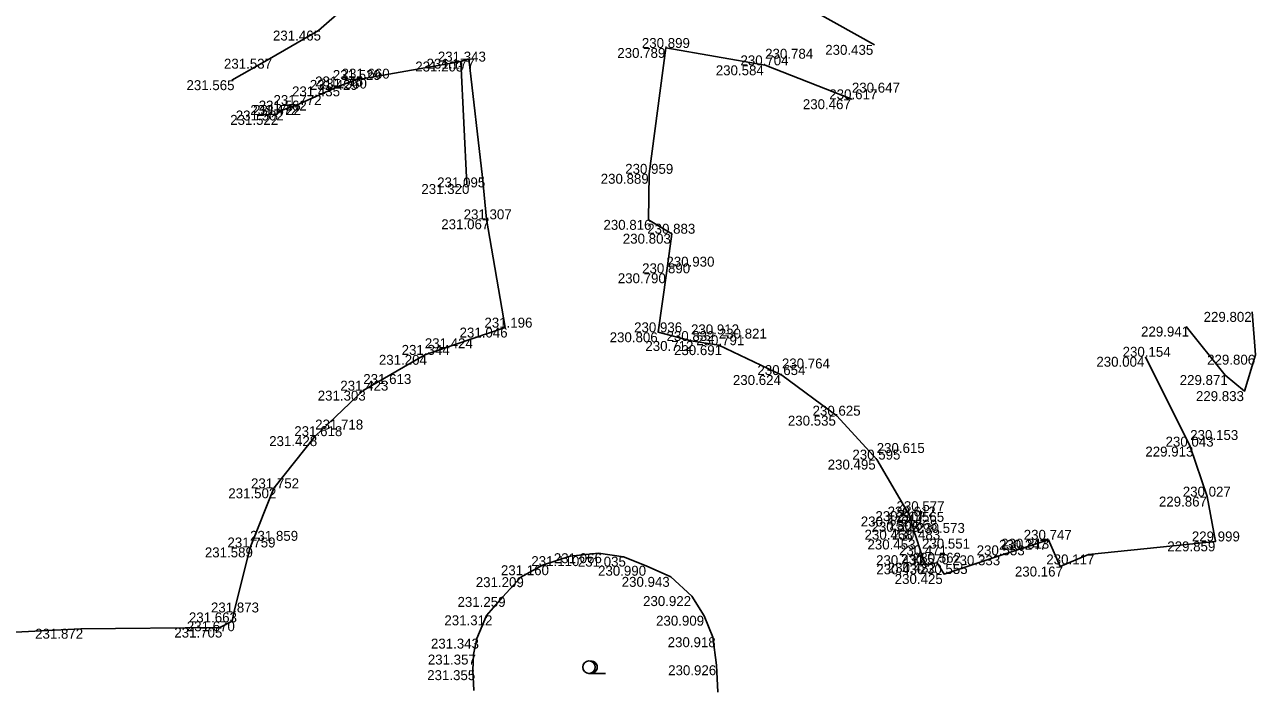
# Model space of a CAD drawing. Extents: x -599516 to -599132, y -1163668 to -1163119.
# Drawn here: x -599477.33 to -599440.16, y -1163341.82 to -1163321.87 of the extents above; entities that cross this region are included whole.
import ezdxf

# ---------------------------------------------------------------- set-up
doc = ezdxf.new("R2010")
doc.units = 0
for name, color, linetype in [('Bod-oznac1', 7, 'Continuous'), ('Bod-oznac2', 7, 'Continuous'), ('Bod-oznac3', 7, 'Continuous'), ('Bod-vyska1', 7, 'Continuous'), ('Bod-vyska2', 7, 'Continuous'), ('Bod-vyska3', 7, 'Continuous'), ('Z_cela-hrobu-dolni-linie', 7, 'Continuous'), ('Z_cela-hrobu-horni-linie', 7, 'Continuous'), ('Z_chodnik', 7, 'Continuous'), ('Z_komunikace', 7, 'Continuous'), ('Z_kultury-znacky', 7, 'Continuous')]:
    doc.layers.add(name, color=color, linetype=linetype)

msp = doc.modelspace()

# ---------------------------------------------------------------- linework, layer by layer
at = {"layer": 'Bod-oznac1'}
for p, q in [((-599468.452, -1163322.051), (-599468.452, -1163322.051)), ((-599457.962, -1163322.576), (-599457.962, -1163322.576)), ((-599451.662, -1163322.483), (-599451.662, -1163322.483)), ((-599469.93, -1163322.901), (-599469.93, -1163322.901)), ((-599464.156, -1163322.986), (-599464.156, -1163322.986)), ((-599463.913, -1163322.9), (-599463.913, -1163322.9)), ((-599454.967, -1163323.1), (-599454.967, -1163323.1)), ((-599471.075, -1163323.549), (-599471.075, -1163323.549)), ((-599467.865, -1163323.737), (-599467.865, -1163323.737)), ((-599467.339, -1163323.541), (-599467.339, -1163323.541)), ((-599467.08, -1163323.502), (-599467.08, -1163323.502)), ((-599452.348, -1163324.124), (-599452.348, -1163324.124)), ((-599469.577, -1163324.465), (-599469.577, -1163324.465)), ((-599469.122, -1163324.298), (-599469.122, -1163324.298)), ((-599469.743, -1163324.597), (-599469.743, -1163324.597)), ((-599458.465, -1163326.375), (-599458.465, -1163326.375)), ((-599463.973, -1163326.683), (-599463.973, -1163326.683)), ((-599463.506, -1163326.485), (-599463.506, -1163326.485)), ((-599463.382, -1163327.748), (-599463.382, -1163327.748)), ((-599458.486, -1163327.766), (-599458.486, -1163327.766)), ((-599457.787, -1163328.184), (-599457.787, -1163328.184)), ((-599457.949, -1163329.378), (-599457.949, -1163329.378)), ((-599440.259, -1163330.544), (-599440.259, -1163330.544)), ((-599462.819, -1163331.018), (-599462.819, -1163331.018)), ((-599458.196, -1163331.16), (-599458.196, -1163331.16)), ((-599442.25, -1163330.987), (-599442.25, -1163330.987)), ((-599457.206, -1163331.422), (-599457.206, -1163331.422)), ((-599456.366, -1163331.549), (-599456.366, -1163331.549)), ((-599465.244, -1163331.841), (-599465.244, -1163331.841)), ((-599443.479, -1163331.899), (-599443.479, -1163331.899)), ((-599440.164, -1163331.837), (-599440.164, -1163331.837)), ((-599454.461, -1163332.451), (-599454.461, -1163332.451)), ((-599441.081, -1163332.45), (-599441.081, -1163332.45)), ((-599467.102, -1163332.921), (-599467.102, -1163332.921)), ((-599440.489, -1163332.937), (-599440.489, -1163332.937)), ((-599452.801, -1163333.677), (-599452.801, -1163333.677)), ((-599468.555, -1163334.295), (-599468.555, -1163334.295)), ((-599442.132, -1163334.611), (-599442.132, -1163334.611)), ((-599451.599, -1163335.003), (-599451.599, -1163335.003)), ((-599469.802, -1163335.87), (-599469.802, -1163335.87)), ((-599441.616, -1163336.12), (-599441.616, -1163336.12)), ((-599450.587, -1163336.722), (-599450.587, -1163336.722)), ((-599450.259, -1163336.56), (-599450.259, -1163336.56)), ((-599450.485, -1163337.12), (-599450.485, -1163337.12)), ((-599450.278, -1163336.882), (-599450.278, -1163336.882)), ((-599450.387, -1163337.416), (-599450.387, -1163337.416)), ((-599446.412, -1163337.424), (-599446.412, -1163337.424)), ((-599441.365, -1163337.473), (-599441.365, -1163337.473)), ((-599470.52, -1163337.655), (-599470.52, -1163337.655)), ((-599460.86, -1163337.918), (-599460.86, -1163337.918)), ((-599459.995, -1163337.83), (-599459.995, -1163337.83)), ((-599459.247, -1163337.934), (-599459.247, -1163337.934)), ((-599450.231, -1163337.89), (-599450.231, -1163337.89)), ((-599447.84, -1163337.892), (-599447.84, -1163337.892)), ((-599445.203, -1163337.867), (-599445.203, -1163337.867)), ((-599461.686, -1163338.193), (-599461.686, -1163338.193)), ((-599458.558, -1163338.209), (-599458.558, -1163338.209)), ((-599450.122, -1163338.165), (-599450.122, -1163338.165)), ((-599449.771, -1163338.116), (-599449.771, -1163338.116)), ((-599446.06, -1163338.233), (-599446.06, -1163338.233)), ((-599462.341, -1163338.553), (-599462.341, -1163338.553)), ((-599457.819, -1163338.544), (-599457.819, -1163338.544)), ((-599449.564, -1163338.457), (-599449.564, -1163338.457)), ((-599462.891, -1163339.149), (-599462.891, -1163339.149)), ((-599457.186, -1163339.125), (-599457.186, -1163339.125)), ((-599471.012, -1163339.618), (-599471.012, -1163339.618)), ((-599463.379, -1163339.705), (-599463.379, -1163339.705)), ((-599456.806, -1163339.717), (-599456.806, -1163339.717)), ((-599475.632, -1163340.11), (-599475.632, -1163340.11)), ((-599471.43, -1163340.076), (-599471.43, -1163340.076)), ((-599471.065, -1163339.885), (-599471.065, -1163339.885)), ((-599463.67, -1163340.408), (-599463.67, -1163340.408)), ((-599456.547, -1163340.366), (-599456.547, -1163340.366)), ((-599463.774, -1163340.89), (-599463.774, -1163340.89)), ((-599456.439, -1163341.212), (-599456.439, -1163341.212)), ((-599463.794, -1163341.361), (-599463.794, -1163341.361))]:
    msp.add_line(p, q, dxfattribs=at)
at = {"layer": 'Bod-oznac2'}
for p, q in [((-599457.962, -1163322.576), (-599457.962, -1163322.576)), ((-599464.156, -1163322.986), (-599464.156, -1163322.986)), ((-599454.967, -1163323.1), (-599454.967, -1163323.1)), ((-599467.865, -1163323.737), (-599467.865, -1163323.737)), ((-599467.339, -1163323.541), (-599467.339, -1163323.541)), ((-599467.08, -1163323.502), (-599467.08, -1163323.502)), ((-599452.348, -1163324.124), (-599452.348, -1163324.124)), ((-599469.577, -1163324.465), (-599469.577, -1163324.465)), ((-599469.122, -1163324.298), (-599469.122, -1163324.298)), ((-599469.743, -1163324.597), (-599469.743, -1163324.597)), ((-599458.465, -1163326.375), (-599458.465, -1163326.375)), ((-599463.382, -1163327.748), (-599463.382, -1163327.748)), ((-599457.787, -1163328.184), (-599457.787, -1163328.184)), ((-599457.949, -1163329.378), (-599457.949, -1163329.378)), ((-599462.819, -1163331.018), (-599462.819, -1163331.018)), ((-599458.196, -1163331.16), (-599458.196, -1163331.16)), ((-599457.206, -1163331.422), (-599457.206, -1163331.422)), ((-599456.366, -1163331.549), (-599456.366, -1163331.549)), ((-599465.244, -1163331.841), (-599465.244, -1163331.841)), ((-599443.479, -1163331.899), (-599443.479, -1163331.899)), ((-599454.461, -1163332.451), (-599454.461, -1163332.451)), ((-599467.102, -1163332.921), (-599467.102, -1163332.921)), ((-599452.801, -1163333.677), (-599452.801, -1163333.677)), ((-599468.555, -1163334.295), (-599468.555, -1163334.295)), ((-599442.132, -1163334.611), (-599442.132, -1163334.611)), ((-599451.599, -1163335.003), (-599451.599, -1163335.003)), ((-599469.802, -1163335.87), (-599469.802, -1163335.87)), ((-599441.616, -1163336.12), (-599441.616, -1163336.12)), ((-599450.587, -1163336.722), (-599450.587, -1163336.722)), ((-599450.259, -1163336.56), (-599450.259, -1163336.56)), ((-599450.485, -1163337.12), (-599450.485, -1163337.12)), ((-599450.278, -1163336.882), (-599450.278, -1163336.882)), ((-599450.387, -1163337.416), (-599450.387, -1163337.416)), ((-599446.412, -1163337.424), (-599446.412, -1163337.424)), ((-599441.365, -1163337.473), (-599441.365, -1163337.473)), ((-599470.52, -1163337.655), (-599470.52, -1163337.655)), ((-599450.231, -1163337.89), (-599450.231, -1163337.89)), ((-599447.84, -1163337.892), (-599447.84, -1163337.892)), ((-599450.122, -1163338.165), (-599450.122, -1163338.165)), ((-599449.771, -1163338.116), (-599449.771, -1163338.116)), ((-599449.564, -1163338.457), (-599449.564, -1163338.457)), ((-599471.012, -1163339.618), (-599471.012, -1163339.618))]:
    msp.add_line(p, q, dxfattribs=at)
at = {"layer": 'Bod-oznac3'}
for p, q in [((-599454.967, -1163323.1), (-599454.967, -1163323.1)), ((-599452.348, -1163324.124), (-599452.348, -1163324.124)), ((-599457.949, -1163329.378), (-599457.949, -1163329.378)), ((-599457.206, -1163331.422), (-599457.206, -1163331.422)), ((-599456.366, -1163331.549), (-599456.366, -1163331.549)), ((-599465.244, -1163331.841), (-599465.244, -1163331.841)), ((-599454.461, -1163332.451), (-599454.461, -1163332.451)), ((-599467.102, -1163332.921), (-599467.102, -1163332.921)), ((-599468.555, -1163334.295), (-599468.555, -1163334.295)), ((-599442.132, -1163334.611), (-599442.132, -1163334.611)), ((-599451.599, -1163335.003), (-599451.599, -1163335.003)), ((-599450.387, -1163337.416), (-599450.387, -1163337.416)), ((-599470.52, -1163337.655), (-599470.52, -1163337.655)), ((-599450.231, -1163337.89), (-599450.231, -1163337.89)), ((-599447.84, -1163337.892), (-599447.84, -1163337.892))]:
    msp.add_line(p, q, dxfattribs=at)
at = {"layer": 'Z_cela-hrobu-dolni-linie'}
msp.add_lwpolyline([(-599450.259, -1163336.56), (-599450.278, -1163336.882), (-599450.485, -1163337.12)], dxfattribs=at)
at = {"layer": 'Z_cela-hrobu-horni-linie'}
for points in [[(-599458.465, -1163326.375), (-599457.962, -1163322.576), (-599454.967, -1163323.1), (-599454.967, -1163323.1), (-599452.348, -1163324.124), (-599452.348, -1163324.124)], [(-599463.973, -1163326.683), (-599464.156, -1163322.986), (-599467.08, -1163323.502), (-599467.339, -1163323.541), (-599467.865, -1163323.737), (-599469.122, -1163324.298), (-599469.577, -1163324.465), (-599469.743, -1163324.597)], [(-599471.012, -1163339.618), (-599470.52, -1163337.655), (-599470.52, -1163337.655), (-599469.802, -1163335.87), (-599468.555, -1163334.295), (-599468.555, -1163334.295), (-599467.102, -1163332.921), (-599467.102, -1163332.921), (-599465.244, -1163331.841), (-599465.244, -1163331.841), (-599462.819, -1163331.018), (-599463.382, -1163327.748)], [(-599450.587, -1163336.722), (-599451.599, -1163335.003), (-599451.599, -1163335.003), (-599452.801, -1163333.677), (-599454.461, -1163332.451), (-599454.461, -1163332.451), (-599456.366, -1163331.549), (-599456.366, -1163331.549), (-599457.206, -1163331.422), (-599457.206, -1163331.422), (-599458.196, -1163331.16), (-599457.949, -1163329.378), (-599457.949, -1163329.378), (-599457.787, -1163328.184)], [(-599445.203, -1163337.867), (-599441.365, -1163337.473), (-599441.616, -1163336.12), (-599442.132, -1163334.611), (-599442.132, -1163334.611), (-599443.479, -1163331.899)], [(-599446.412, -1163337.424), (-599447.84, -1163337.892), (-599447.84, -1163337.892), (-599449.564, -1163338.457), (-599449.771, -1163338.116), (-599450.122, -1163338.165), (-599450.231, -1163337.89), (-599450.231, -1163337.89), (-599450.387, -1163337.416), (-599450.387, -1163337.416), (-599450.485, -1163337.12), (-599450.278, -1163336.882), (-599450.259, -1163336.56)]]:
    msp.add_lwpolyline(points, dxfattribs=at)
at = {"layer": 'Z_chodnik'}
for points in [[(-599451.502, -1163320.419), (-599453.908, -1163320.404), (-599454.026, -1163321.164), (-599451.662, -1163322.483)], [(-599470.993, -1163321.486), (-599467.662, -1163321.352), (-599468.452, -1163322.051), (-599469.93, -1163322.901), (-599471.075, -1163323.549)], [(-599457.962, -1163322.576), (-599454.967, -1163323.1), (-599452.348, -1163324.124)], [(-599469.743, -1163324.597), (-599469.577, -1163324.465), (-599469.122, -1163324.298), (-599467.865, -1163323.737), (-599467.339, -1163323.541), (-599467.08, -1163323.502), (-599464.156, -1163322.986), (-599463.913, -1163322.9)], [(-599440.259, -1163330.544), (-599440.164, -1163331.837), (-599440.489, -1163332.937), (-599441.081, -1163332.45), (-599442.25, -1163330.987)], [(-599443.479, -1163331.899), (-599442.132, -1163334.611), (-599441.616, -1163336.12), (-599441.365, -1163337.473)], [(-599456.401, -1163342.025), (-599456.439, -1163341.212), (-599456.547, -1163340.366), (-599456.806, -1163339.717), (-599457.186, -1163339.125), (-599457.819, -1163338.544), (-599458.558, -1163338.209), (-599459.247, -1163337.934), (-599459.995, -1163337.83), (-599460.86, -1163337.918), (-599461.686, -1163338.193), (-599462.341, -1163338.553), (-599462.891, -1163339.149), (-599463.379, -1163339.705), (-599463.67, -1163340.408), (-599463.774, -1163340.89), (-599463.794, -1163341.361)], [(-599463.794, -1163341.361), (-599463.764, -1163341.978)]]:
    msp.add_lwpolyline(points, dxfattribs=at)
at = {"layer": 'Z_komunikace'}
for points in [[(-599458.486, -1163327.766), (-599458.465, -1163326.375), (-599457.962, -1163322.576)], [(-599463.913, -1163322.9), (-599463.506, -1163326.485), (-599463.382, -1163327.748), (-599462.819, -1163331.018)], [(-599446.06, -1163338.233), (-599446.412, -1163337.424), (-599447.84, -1163337.892), (-599449.564, -1163338.457), (-599449.771, -1163338.116), (-599450.122, -1163338.165), (-599450.231, -1163337.89), (-599450.387, -1163337.416), (-599450.485, -1163337.12), (-599450.587, -1163336.722), (-599451.599, -1163335.003), (-599452.801, -1163333.677), (-599454.461, -1163332.451), (-599456.366, -1163331.549), (-599457.206, -1163331.422), (-599458.196, -1163331.16), (-599457.949, -1163329.378), (-599457.787, -1163328.184), (-599458.486, -1163327.766)], [(-599462.819, -1163331.018), (-599465.244, -1163331.841), (-599467.102, -1163332.921), (-599468.555, -1163334.295), (-599469.802, -1163335.87), (-599470.52, -1163337.655), (-599471.012, -1163339.618), (-599471.065, -1163339.885), (-599471.43, -1163340.076), (-599475.632, -1163340.11), (-599480.187, -1163340.348)], [(-599441.365, -1163337.473), (-599445.203, -1163337.867), (-599446.06, -1163338.233)]]:
    msp.add_lwpolyline(points, dxfattribs=at)
at = {"layer": 'Z_kultury-znacky'}
msp.add_line((-599460.287, -1163341.458), (-599459.787, -1163341.458), dxfattribs=at)
msp.add_circle((-599460.287, -1163341.27), 0.188, dxfattribs=at)
msp.add_arc((-599460.224, -1163341.27), 0.188, 260.4059, 99.5941, dxfattribs=at)

# ---------------------------------------------------------------- texts
at = {"layer": 'Bod-vyska1'}
for s, p in [('231.465', (-599469.83, -1163322.351)), ('230.789', (-599459.432, -1163322.876)), ('230.435', (-599453.153, -1163322.783)), ('231.537', (-599471.309, -1163323.201)), ('231.203', (-599465.532, -1163323.286)), ('231.177', (-599465.19, -1163323.2)), ('230.584', (-599456.458, -1163323.4)), ('231.565', (-599472.441, -1163323.849)), ('231.435', (-599469.254, -1163324.037)), ('231.429', (-599468.717, -1163323.841)), ('231.360', (-599468.444, -1163323.802)), ('230.467', (-599453.829, -1163324.424)), ('231.502', (-599470.953, -1163324.765)), ('231.472', (-599470.513, -1163324.598)), ('231.522', (-599471.121, -1163324.897)), ('230.889', (-599459.933, -1163326.675)), ('231.320', (-599465.349, -1163326.983)), ('231.095', (-599464.87, -1163326.785)), ('231.067', (-599464.748, -1163328.048)), ('230.816', (-599459.85, -1163328.066)), ('230.803', (-599459.265, -1163328.484)), ('230.790', (-599459.417, -1163329.678)), ('229.802', (-599441.727, -1163330.844)), ('231.046', (-599464.195, -1163331.318)), ('230.806', (-599459.662, -1163331.46)), ('229.941', (-599443.616, -1163331.287)), ('230.712', (-599458.584, -1163331.722)), ('230.691', (-599457.719, -1163331.849)), ('231.204', (-599466.631, -1163332.141)), ('230.004', (-599444.966, -1163332.199)), ('229.806', (-599441.621, -1163332.137)), ('230.624', (-599455.941, -1163332.751)), ('229.871', (-599442.449, -1163332.75)), ('231.303', (-599468.478, -1163333.221)), ('229.833', (-599441.959, -1163333.237)), ('230.535', (-599454.281, -1163333.977)), ('231.428', (-599469.944, -1163334.595)), ('229.913', (-599443.487, -1163334.911)), ('230.495', (-599453.079, -1163335.303)), ('231.502', (-599471.178, -1163336.17)), ('229.867', (-599443.077, -1163336.42)), ('230.472', (-599452.08, -1163337.022)), ('230.517', (-599451.637, -1163336.86)), ('230.468', (-599451.965, -1163337.42)), ('230.505', (-599451.756, -1163337.182)), ('230.453', (-599451.878, -1163337.716)), ('230.247', (-599447.905, -1163337.724)), ('229.859', (-599442.824, -1163337.773)), ('231.589', (-599471.886, -1163337.955)), ('231.110', (-599462.028, -1163338.218)), ('231.066', (-599461.348, -1163338.13)), ('231.035', (-599460.623, -1163338.234)), ('230.431', (-599451.618, -1163338.19)), ('230.333', (-599449.32, -1163338.192)), ('230.117', (-599446.477, -1163338.167)), ('231.160', (-599462.946, -1163338.493)), ('230.990', (-599460.013, -1163338.509)), ('230.430', (-599451.611, -1163338.465)), ('230.432', (-599451.262, -1163338.416)), ('230.167', (-599447.426, -1163338.533)), ('231.209', (-599463.705, -1163338.853)), ('230.943', (-599459.299, -1163338.844)), ('230.425', (-599451.055, -1163338.757)), ('231.259', (-599464.257, -1163339.449)), ('230.922', (-599458.654, -1163339.425)), ('231.663', (-599472.367, -1163339.918)), ('231.312', (-599464.653, -1163340.005)), ('230.909', (-599458.261, -1163340.017)), ('231.872', (-599477.011, -1163340.41)), ('231.705', (-599472.808, -1163340.376)), ('231.670', (-599472.431, -1163340.185)), ('231.343', (-599465.059, -1163340.708)), ('230.918', (-599457.911, -1163340.666)), ('231.357', (-599465.153, -1163341.19)), ('230.926', (-599457.896, -1163341.512)), ('231.355', (-599465.172, -1163341.661))]:
    msp.add_text(s, height=0.3, dxfattribs=at).set_placement(p)
at = {"layer": 'Bod-vyska2'}
for s, p in [('230.899', (-599458.69, -1163322.576)), ('231.343', (-599464.85, -1163322.986)), ('230.704', (-599455.712, -1163323.1)), ('231.775', (-599468.556, -1163323.737)), ('231.529', (-599468.022, -1163323.541)), ('231.660', (-599467.756, -1163323.502)), ('231.562', (-599470.26, -1163324.465)), ('231.772', (-599469.813, -1163324.298)), ('230.617', (-599453.031, -1163324.124)), ('231.722', (-599470.433, -1163324.597)), ('230.959', (-599459.193, -1163326.375)), ('231.307', (-599464.071, -1163327.748)), ('230.883', (-599458.527, -1163328.184)), ('230.890', (-599458.682, -1163329.378)), ('231.196', (-599463.444, -1163331.018)), ('230.936', (-599458.924, -1163331.16)), ('230.832', (-599457.946, -1163331.422)), ('230.791', (-599457.049, -1163331.549)), ('231.344', (-599465.944, -1163331.841)), ('230.154', (-599444.173, -1163331.899)), ('230.654', (-599455.201, -1163332.451)), ('231.423', (-599467.796, -1163332.921)), ('230.625', (-599453.535, -1163333.677)), ('231.618', (-599469.186, -1163334.295)), ('230.043', (-599442.876, -1163334.611)), ('230.595', (-599452.333, -1163335.003)), ('231.752', (-599470.492, -1163335.87)), ('230.027', (-599442.356, -1163336.12)), ('230.612', (-599451.269, -1163336.722)), ('230.577', (-599451.001, -1163336.56)), ('230.568', (-599451.219, -1163337.12)), ('230.565', (-599451.012, -1163336.882)), ('230.483', (-599451.132, -1163337.416)), ('230.747', (-599447.159, -1163337.424)), ('229.999', (-599442.083, -1163337.473)), ('231.759', (-599471.204, -1163337.655)), ('230.471', (-599450.925, -1163337.89)), ('230.570', (-599450.862, -1163338.165)), ('230.562', (-599450.505, -1163338.116)), ('230.553', (-599448.58, -1163337.892)), ('230.555', (-599450.304, -1163338.457)), ('231.873', (-599471.702, -1163339.618))]:
    msp.add_text(s, height=0.3, dxfattribs=at).set_placement(p)
at = {"layer": 'Bod-vyska3'}
for s, p in [('230.784', (-599454.967, -1163322.9)), ('230.647', (-599452.348, -1163323.924)), ('230.930', (-599457.949, -1163329.178)), ('230.912', (-599457.206, -1163331.222)), ('230.821', (-599456.366, -1163331.349)), ('231.424', (-599465.244, -1163331.641)), ('230.764', (-599454.461, -1163332.251)), ('231.613', (-599467.102, -1163332.721)), ('231.718', (-599468.555, -1163334.095)), ('230.153', (-599442.132, -1163334.411)), ('230.615', (-599451.599, -1163334.803)), ('231.859', (-599470.52, -1163337.455)), ('230.573', (-599450.387, -1163337.216)), ('230.551', (-599450.231, -1163337.69)), ('230.813', (-599447.84, -1163337.692))]:
    msp.add_text(s, height=0.3, dxfattribs=at).set_placement(p)

doc.saveas('drawing.dxf')
